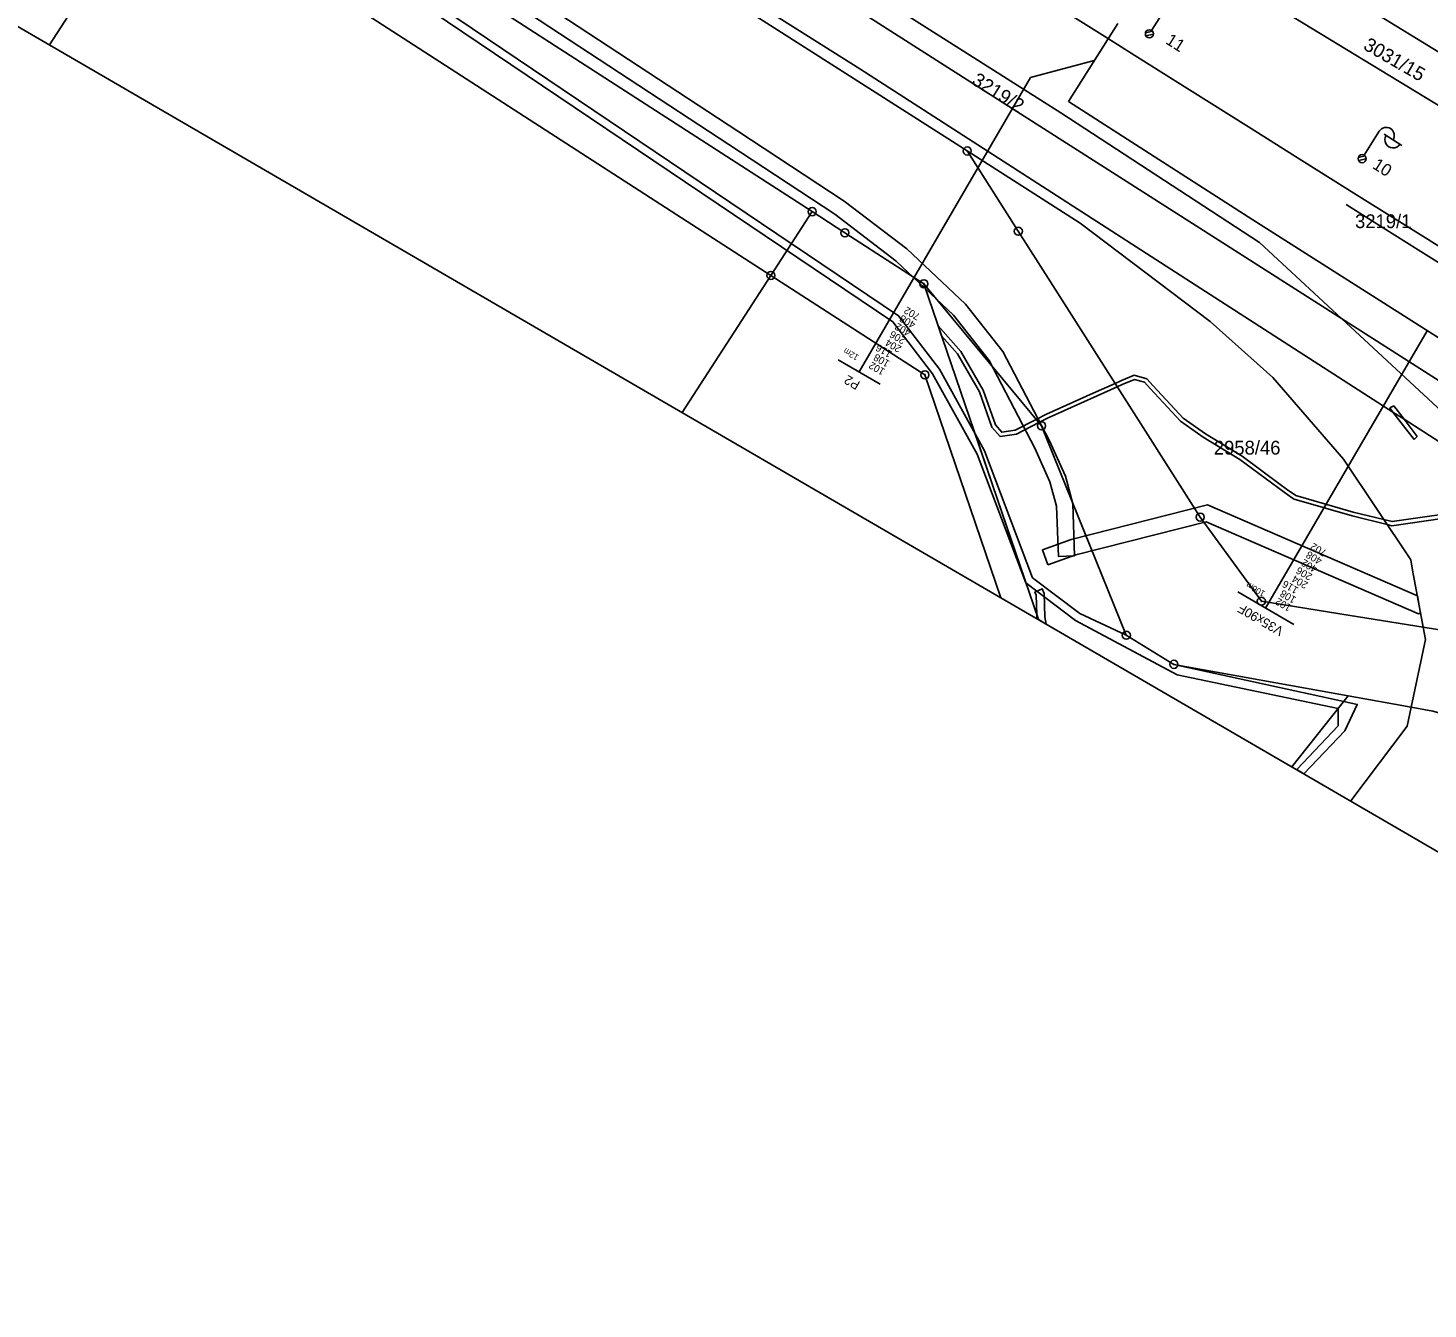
# Model space of a CAD drawing. Extents: x -620765 to -620328, y -1122680 to -1122340.
# Drawn here: x -620673.3 to -620500.6, y -1122679.9 to -1122521.8 of the extents above; entities that cross this region are included whole.
import ezdxf

# ---------------------------------------------------------------- set-up
doc = ezdxf.new("R2010")
doc.units = 0
for name, color, linetype in [('HranDP', 7, 'Continuous'), ('Hranice parcel', 7, 'Continuous'), ('Parcelní čísla', 7, 'Continuous'), ('Rámečky-tisk', 7, 'Continuous'), ('Vnitřní kresba', 7, 'Continuous'), ('Vrstva 1', 7, 'Continuous'), ('Vrstva 14', 7, 'Continuous'), ('Vrstva 25', 7, 'Continuous'), ('Vrstva 33', 7, 'Continuous'), ('Věcná břemena k části', 7, 'Continuous'), ('Značky bodu BP', 7, 'Continuous')]:
    doc.layers.add(name, color=color, linetype=linetype)

msp = doc.modelspace()

# ---------------------------------------------------------------- linework, layer by layer
at = {"layer": 'HranDP'}
for p, q in [((-620445.8, -1122563.95), (-620552.09, -1122499.2)), ((-620511.29, -1122557.64), (-620485.21, -1122574.33))]:
    msp.add_line(p, q, dxfattribs=at)
msp.add_lwpolyline([(-620733.18, -1122413.37), (-620679.51, -1122447.56), (-620545.92, -1122532.26), (-620521.41, -1122548.27), (-620511.29, -1122557.64)], dxfattribs=at)
at = {"layer": 'Hranice parcel'}
for p, q in [((-620660.74, -1122490.09), (-620576.58, -1122544.45)), ((-620548.9, -1122494.24), (-620475.79, -1122539.24)), ((-620445.8, -1122563.95), (-620552.09, -1122499.2)), ((-620581.67, -1122552.32), (-620576.58, -1122544.45)), ((-620581.67, -1122552.32), (-620592.6, -1122569.24)), ((-620511.29, -1122557.64), (-620485.21, -1122574.33)), ((-620510.44, -1122604.21), (-620502.69, -1122605.61))]:
    msp.add_line(p, q, dxfattribs=at)
for points in [[(-620733.18, -1122413.37), (-620679.51, -1122447.56), (-620545.92, -1122532.26), (-620521.41, -1122548.27), (-620511.29, -1122557.64)], [(-620734, -1122414.78), (-620645.72, -1122471.03), (-620587.17, -1122509.18), (-620511.29, -1122557.64)], [(-620557.45, -1122536.96), (-620684.91, -1122455.63), (-620738.08, -1122421.79)], [(-620581.67, -1122552.32), (-620657.43, -1122503.38), (-620670.66, -1122523.85)], [(-620501.2, -1122595.75), (-620510.22, -1122594.3), (-620521.17, -1122592.53), (-620528.72, -1122582.15), (-620536.04, -1122570.64), (-620547.19, -1122553.1), (-620551.15, -1122546.87), (-620557.45, -1122536.96)], [(-620557.45, -1122536.96), (-620543.5, -1122545.86), (-620527.5, -1122558.02), (-620519.77, -1122564.93), (-620511.02, -1122574.99), (-620502.74, -1122587.44), (-620502.51, -1122588.68), (-620501.2, -1122595.75)], [(-620576.58, -1122544.45), (-620572.54, -1122547.06), (-620562.8, -1122553.35)], [(-620581.67, -1122552.32), (-620562.67, -1122564.59), (-620553.29, -1122592.1)], [(-620562.8, -1122553.35), (-620548.28, -1122570.88), (-620537.83, -1122596.73), (-620531.96, -1122600.32), (-620510.44, -1122604.21)], [(-620562.8, -1122553.35), (-620548.67, -1122594.78)], [(-620511.29, -1122557.64), (-620498.35, -1122569.65), (-620494.61, -1122575.85)], [(-620502.69, -1122605.61), (-620500.92, -1122597.26), (-620501.2, -1122595.75)], [(-620501.2, -1122595.75), (-620497.68, -1122596.32), (-620483.58, -1122598.6), (-620482.88, -1122598.82)], [(-620517.4, -1122612.97), (-620510.44, -1122604.21)], [(-620502.69, -1122605.61), (-620503.19, -1122607.95), (-620510.15, -1122617.18)], [(-620496.31, -1122607.11), (-620500, -1122606.09), (-620502.69, -1122605.61)]]:
    msp.add_lwpolyline(points, dxfattribs=at)
at = {"layer": 'Rámečky-tisk'}
msp.add_lwpolyline([(-620690.75, -1122340.39), (-620765.39, -1122468.77), (-620402.31, -1122679.89)], dxfattribs=at)
at = {"layer": 'Vnitřní kresba'}
for p, q in [((-620570.69, -1122526.84), (-620613.12, -1122500)), ((-620504.94, -1122569.2), (-620570.69, -1122526.84)), ((-620505.32, -1122568.68), (-620504.84, -1122568.4)), ((-620504.94, -1122569.2), (-620505.32, -1122568.68)), ((-620503.56, -1122570.07), (-620504.94, -1122569.2)), ((-620502.33, -1122572.56), (-620504.94, -1122569.2)), ((-620504.84, -1122568.4), (-620503.56, -1122570.07)), ((-620494.61, -1122575.85), (-620503.56, -1122570.07)), ((-620503.56, -1122570.07), (-620501.96, -1122572.22)), ((-620501.96, -1122572.22), (-620502.33, -1122572.56))]:
    msp.add_line(p, q, dxfattribs=at)
at = {"layer": 'Vrstva 1'}
msp.add_line((-620544.95, -1122530.86), (-620538.89, -1122521.21), dxfattribs=at)
for points in [[(-620545.74, -1122519.52), (-620540.16, -1122523.03), (-620536.76, -1122525.16), (-620530.04, -1122529.4), (-620522.74, -1122534), (-620516.18, -1122538.13), (-620510.88, -1122541.46), (-620509.77, -1122542.15), (-620508.12, -1122543.19), (-620500.94, -1122547.69), (-620490.94, -1122553.98)], [(-620456.11, -1122587.12), (-620500.01, -1122559.59), (-620522.22, -1122545.45), (-620544.95, -1122530.86)]]:
    msp.add_lwpolyline(points, dxfattribs=at)
at = {"layer": 'Vrstva 14'}
msp.add_lwpolyline([(-620510.69, -1122543.55), (-620509.04, -1122544.63), (-620501.84, -1122549.15), (-620491.85, -1122555.41), (-620483.32, -1122560.77), (-620478.25, -1122563.97), (-620473.97, -1122566.66), (-620465.4, -1122572.05), (-620457.72, -1122576.88), (-620450.01, -1122581.72), (-620442.29, -1122586.56), (-620434.63, -1122591.38), (-620426.95, -1122596.21), (-620419.24, -1122601.09), (-620411.54, -1122605.96), (-620403.8, -1122610.84), (-620395.25, -1122616.25), (-620387.51, -1122621.12), (-620379.87, -1122625.94), (-620375.57, -1122628.64), (-620373.33, -1122630.05)], dxfattribs=at)
at = {"layer": 'Vrstva 25'}
for p, q in [((-620534.71, -1122522.08), (-620532.84, -1122519.12)), ((-620535.46, -1122522.37), (-620534.6, -1122522.18)), ((-620535.41, -1122522.74), (-620534.48, -1122522.53)), ((-620508.48, -1122537.48), (-620506.62, -1122534.52)), ((-620506.02, -1122534.89), (-620503.82, -1122536.27)), ((-620509.23, -1122537.78), (-620508.37, -1122537.58)), ((-620509.18, -1122538.15), (-620508.25, -1122537.94))]:
    msp.add_line(p, q, dxfattribs=at)
for centre in [(-620534.98, -1122522.5), (-620508.74, -1122537.91)]:
    msp.add_circle(centre, 0.5, dxfattribs=at)
for centre, start, end in [((-620505.77, -1122535.05), 327.8645, 147.8645), ((-620504.93, -1122535.59), 147.162, 328.5671)]:
    msp.add_arc(centre, 1, start, end, dxfattribs=at)
at = {"layer": 'Vrstva 33'}
for p, q in [((-620549.65, -1122527.89), (-620541.78, -1122525.81)), ((-620549.65, -1122527.89), (-620570.78, -1122564.23)), ((-620500.73, -1122559.14), (-620520.64, -1122593.38)), ((-620573.37, -1122562.72), (-620568.18, -1122565.74)), ((-620524.09, -1122591.37), (-620517.18, -1122595.39))]:
    msp.add_line(p, q, dxfattribs=at)
at = {"layer": 'Věcná břemena k části'}
for p, q in [((-620548.85, -1122594.68), (-620547.7, -1122595.35)), ((-620516.81, -1122613.31), (-620515.92, -1122613.83))]:
    msp.add_line(p, q, dxfattribs=at)
for points in [[(-620662.49, -1122492.8), (-620663.99, -1122495.13), (-620660.86, -1122494.48), (-620566.61, -1122558.04), (-620561.72, -1122564.46), (-620556.24, -1122574.37), (-620550.21, -1122590.27), (-620556.49, -1122571.86), (-620560.88, -1122563.9), (-620565.91, -1122557.3), (-620661.78, -1122492.65)], [(-620551.52, -1122571.42), (-620553.2, -1122571.67), (-620553.96, -1122570.77), (-620555.49, -1122566.47), (-620558.24, -1122561.71), (-620561.03, -1122558.53), (-620560.61, -1122559.77), (-620558.64, -1122562.01), (-620555.95, -1122566.69), (-620554.4, -1122571.03), (-620553.4, -1122572.21), (-620551.36, -1122571.9), (-620548.6, -1122570.49), (-620547.46, -1122569.91), (-620541.41, -1122567.17), (-620538.95, -1122566.06), (-620538.32, -1122565.78), (-620536.81, -1122565.17), (-620535.58, -1122565.51), (-620534.89, -1122566.28), (-620531.14, -1122570.32), (-620528.34, -1122572.29), (-620523.83, -1122575.03), (-620518.35, -1122579.09), (-620517.46, -1122579.72), (-620517.13, -1122579.95), (-620509.95, -1122582.01), (-620505.65, -1122583.07), (-620506.06, -1122582.46), (-620509.83, -1122581.53), (-620516.91, -1122579.49), (-620518.05, -1122578.69), (-620518.83, -1122578.11), (-620523.55, -1122574.61), (-620528.06, -1122571.87), (-620530.8, -1122569.94), (-620534.53, -1122565.94), (-620535.3, -1122565.07), (-620536.85, -1122564.65), (-620538.52, -1122565.32), (-620539.22, -1122565.64), (-620541.91, -1122566.85), (-620547.68, -1122569.45), (-620548.93, -1122570.09)], [(-620505.65, -1122583.07), (-620505.06, -1122583.21), (-620494.61, -1122581.71), (-620493.3, -1122581.78), (-620491.64, -1122580.78), (-620491.9, -1122580.35), (-620493.42, -1122581.28), (-620494.63, -1122581.21), (-620505.04, -1122582.71), (-620506.06, -1122582.46)], [(-620547.49, -1122588.06), (-620544.04, -1122586.82), (-620527.96, -1122582.73), (-620501.79, -1122594.1), (-620501.53, -1122593.99), (-620501.92, -1122591.86), (-620527.8, -1122580.63), (-620544.62, -1122584.9), (-620548.17, -1122586.18)]]:
    msp.add_lwpolyline(points, close=True, dxfattribs=at)
for points in [[(-620611.43, -1122520.03), (-620586.86, -1122536.18), (-620573.8, -1122544.78), (-620566.2, -1122550.57), (-620559.13, -1122557.24), (-620554.74, -1122562.8), (-620549.11, -1122573.63), (-620547.24, -1122577.78), (-620546.44, -1122580.81), (-620546.21, -1122587), (-620544.21, -1122586.92), (-620544.44, -1122580.51), (-620545.34, -1122577.1), (-620547.31, -1122572.75), (-620553.06, -1122561.7), (-620557.65, -1122555.88), (-620564.9, -1122549.05), (-620572.64, -1122543.14), (-620585.76, -1122534.5), (-620610.33, -1122518.37)], [(-620515.92, -1122613.83), (-620510.87, -1122608.51), (-620509.33, -1122605.27), (-620511, -1122604.91), (-620531.96, -1122600.32), (-620537.83, -1122596.73), (-620543.57, -1122594.05), (-620549.38, -1122589.64), (-620555.33, -1122573.96), (-620556.49, -1122571.86), (-620550.21, -1122590.27), (-620544.11, -1122594.89), (-620531.56, -1122601.62), (-620511.69, -1122605.79), (-620511.71, -1122607.93), (-620516.81, -1122613.31)], [(-620547.7, -1122595.35), (-620547.87, -1122594.46), (-620547.94, -1122591.57), (-620548.19, -1122591), (-620549.11, -1122591.4), (-620548.94, -1122591.79), (-620548.88, -1122594.18), (-620548.87, -1122594.56), (-620548.85, -1122594.68)]]:
    msp.add_lwpolyline(points, dxfattribs=at)
at = {"layer": 'Značky bodu BP'}
for centre, radius in [((-620557.45, -1122536.96), 0.5), ((-620557.45, -1122536.96), 0.0303), ((-620576.58, -1122544.45), 0.5), ((-620576.58, -1122544.45), 0.0303), ((-620572.54, -1122547.06), 0.5), ((-620572.54, -1122547.06), 0.0303), ((-620551.15, -1122546.87), 0.5), ((-620551.15, -1122546.87), 0.0303), ((-620581.67, -1122552.32), 0.5), ((-620581.67, -1122552.32), 0.0303), ((-620562.8, -1122553.35), 0.5), ((-620562.8, -1122553.35), 0.0303), ((-620562.67, -1122564.59), 0.5), ((-620562.67, -1122564.59), 0.0303), ((-620548.28, -1122570.88), 0.5), ((-620548.28, -1122570.88), 0.0303), ((-620528.72, -1122582.15), 0.5), ((-620528.72, -1122582.15), 0.0303), ((-620521.17, -1122592.53), 0.5), ((-620521.17, -1122592.53), 0.0303), ((-620537.83, -1122596.73), 0.5), ((-620537.83, -1122596.73), 0.0303), ((-620531.96, -1122600.32), 0.5), ((-620531.96, -1122600.32), 0.0303)]:
    msp.add_circle(centre, radius, dxfattribs=at)

# ---------------------------------------------------------------- texts
at = {"layer": 'Parcelní čísla'}
for s, rotation, p in [('3031/15', 330, (-620508.71, -1122524.33)), ('3219/2', 328, (-620557.01, -1122528.62))]:
    msp.add_text(s, height=1.7, rotation=rotation, dxfattribs=at).set_placement(p)
for s, p in [('3219/1', (-620509.61, -1122546.48)), ('2958/46', (-620527.03, -1122574.43))]:
    msp.add_text(s, height=1.7, dxfattribs=at).set_placement(p)
at = {"layer": 'Vrstva 25'}
for s, rotation, p in [('11', 327.7645, (-620533.09, -1122523.63)), ('10', 327.8645, (-620507.58, -1122539.02))]:
    msp.add_text(s, height=1.5, rotation=rotation, dxfattribs=at).set_placement(p)
at = {"layer": 'Vrstva 33'}
for s, height, p in [('702', 0.9, (-620563.18, -1122557.14)), ('408', 0.9, (-620563.73, -1122558.15)), ('206', 0.9, (-620564.95, -1122560.1)), ('402', 0.9, (-620564.31, -1122559.14)), ('12m', 0.75, (-620570.76, -1122562.21)), ('116', 0.9, (-620566.66, -1122561.76)), ('204', 0.9, (-620565.47, -1122561.13)), ('102', 0.9, (-620567.51, -1122563.93)), ('108', 0.9, (-620566.93, -1122562.94)), ('P2', 1.15, (-620570.56, -1122565.51)), ('702', 0.9, (-620513.04, -1122586.29)), ('408', 0.9, (-620513.59, -1122587.3)), ('206', 0.9, (-620514.81, -1122589.25)), ('402', 0.9, (-620514.17, -1122588.29)), ('106m', 0.75, (-620520.62, -1122591.37)), ('116', 0.9, (-620516.52, -1122590.92)), ('204', 0.9, (-620515.33, -1122590.28)), ('102', 0.9, (-620517.37, -1122593.08)), ('108', 0.9, (-620516.79, -1122592.09)), ('V35x90F', 1.15, (-620518.32, -1122595.88))]:
    msp.add_text(s, height=height, rotation=149.8236, dxfattribs=at).set_placement(p)

doc.saveas('drawing.dxf')
